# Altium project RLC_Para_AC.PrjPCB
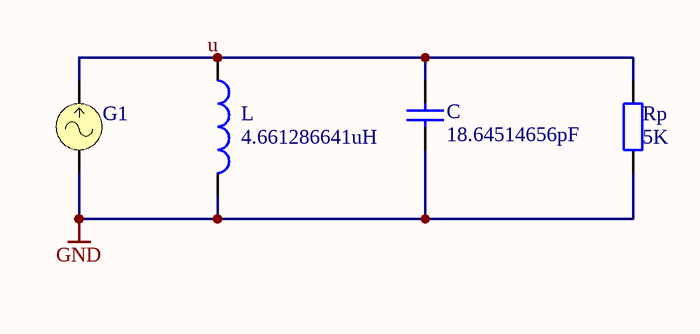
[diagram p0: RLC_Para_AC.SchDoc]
1 sheet, 4 parts. Net scope: global (net labels, ports and power ports of the same name join across sheets).

## Sheet RLC_Para_AC.SchDoc
size A4

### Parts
C  value 18.64514656pF  [RAD-0.3]  (hidden comment: Cap)
G1  ISIN  (value not drawn)
L  value 4.661286641uH  [0402-A]  (hidden comment: Inductor)
Rp  value 5K  [AXIAL-0.4]  (hidden comment: Res2)

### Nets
GND: C.1 G1.1 L.2 Rp.2
u: C.2 G1.2 L.1 Rp.1

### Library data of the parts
C = Cap: Capacitor
G1 = ISIN: Sinusoidal Current Source
L = Inductor: Code_IEC: 1005
Rp = Res2: Resistor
